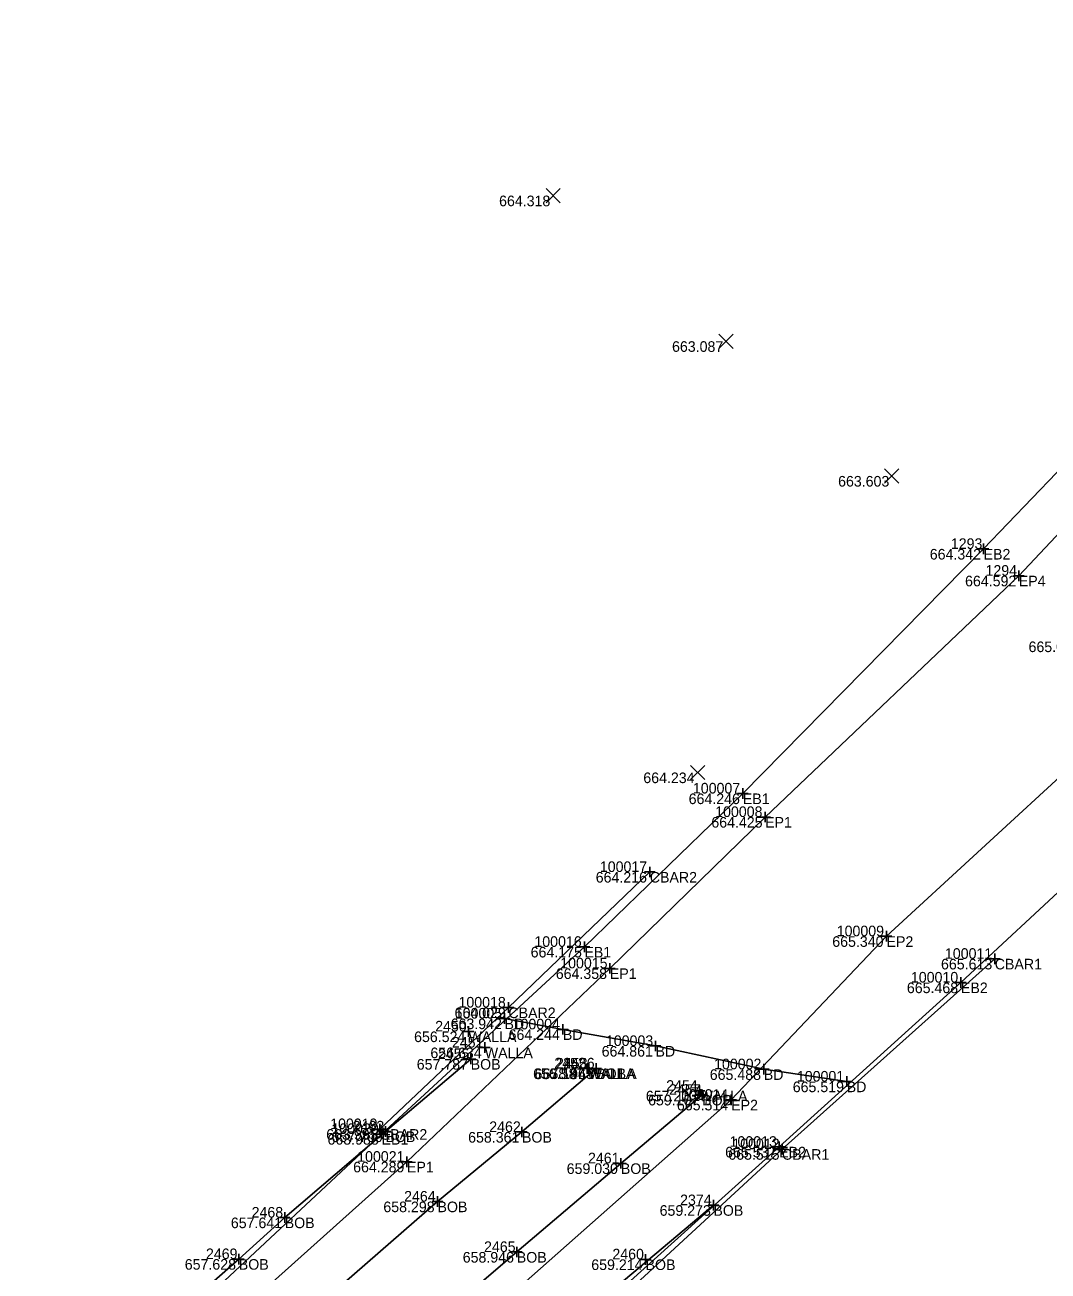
# Model space of a CAD drawing. Extents: x 2197382 to 2204062, y 634117 to 636522.
# Drawn here: x 2202757.5 to 2202854.1, y 635445.9 to 635563.6 of the extents above; entities that cross this region are included whole.
import ezdxf

# ---------------------------------------------------------------- set-up
doc = ezdxf.new("R2010")
doc.units = 0
for name, color, linetype in [('_CIVIL_CONSTRUCTION', 7, 'Continuous'), ('BR_X_SV_Abut', 7, 'Continuous'), ('BR_X_SV_Abut_Text', 7, 'Continuous'), ('BR_X_SV_Bottom_of_Beam', 7, 'Continuous'), ('BR_X_SV_Bottom_of_Beam_Text', 7, 'Continuous'), ('BR_X_SV_Deck_Top', 7, 'Continuous'), ('BR_X_SV_Deck_Top_Text', 7, 'Continuous'), ('GE_P_Alignment_100_Distances', 7, 'Continuous'), ('GE_X_Alignment', 7, 'Continuous'), ('RD_X_Concrete_Barrier', 7, 'Continuous'), ('RW_X_CL_100_Curve_Data', 7, 'Continuous'), ('SH_Border', 7, 'Continuous'), ('SH_Cut_Line', 7, 'Continuous'), ('SH_Data', 7, 'Continuous')]:
    doc.layers.add(name, color=color, linetype=linetype)

msp = doc.modelspace()

# ---------------------------------------------------------------- linework, layer by layer
at = {"layer": '_CIVIL_CONSTRUCTION'}
for p, q in [((2202847.99, 635514.61), (2202847.99, 635513.61)), ((2202847.49, 635514.11), (2202848.49, 635514.11)), ((2202847.99, 635514.11), (2202847.99, 635514.11)), ((2202850.81, 635511.58), (2202851.81, 635511.58)), ((2202851.31, 635512.08), (2202851.31, 635511.08)), ((2202851.31, 635511.58), (2202851.31, 635511.58)), ((2202824.77, 635491.02), (2202825.77, 635491.02)), ((2202825.27, 635491.52), (2202825.27, 635490.52)), ((2202825.27, 635491.02), (2202825.27, 635491.02)), ((2202826.87, 635488.8), (2202827.87, 635488.8)), ((2202827.37, 635489.3), (2202827.37, 635488.3)), ((2202827.37, 635488.8), (2202827.37, 635488.8)), ((2202816.49, 635484.11), (2202816.49, 635483.11)), ((2202815.99, 635483.61), (2202816.99, 635483.61)), ((2202816.49, 635483.61), (2202816.49, 635483.61)), ((2202838.83, 635478.04), (2202838.83, 635477.04)), ((2202810.32, 635477.04), (2202810.32, 635476.04)), ((2202838.33, 635477.54), (2202839.33, 635477.54)), ((2202838.83, 635477.54), (2202838.83, 635477.54)), ((2202809.82, 635476.54), (2202810.82, 635476.54)), ((2202810.32, 635476.54), (2202810.32, 635476.54)), ((2202849.04, 635475.91), (2202849.04, 635474.91)), ((2202812.22, 635474.51), (2202813.22, 635474.51)), ((2202812.72, 635475.01), (2202812.72, 635474.01)), ((2202812.72, 635474.51), (2202812.72, 635474.51)), ((2202848.54, 635475.41), (2202849.54, 635475.41)), ((2202849.04, 635475.41), (2202849.04, 635475.41)), ((2202845.85, 635473.67), (2202845.85, 635472.67)), ((2202845.35, 635473.17), (2202846.35, 635473.17)), ((2202845.85, 635473.17), (2202845.85, 635473.17)), ((2202803.15, 635471.31), (2202803.15, 635470.31)), ((2202802.28, 635469.77), (2202803.28, 635469.77)), ((2202802.65, 635470.81), (2202803.65, 635470.81)), ((2202802.78, 635470.27), (2202802.78, 635469.27)), ((2202802.78, 635469.77), (2202802.78, 635469.77)), ((2202803.15, 635470.81), (2202803.15, 635470.81)), ((2202799.38, 635469.05), (2202799.38, 635468.05)), ((2202807.79, 635468.75), (2202808.79, 635468.75)), ((2202808.29, 635469.25), (2202808.29, 635468.25)), ((2202808.29, 635468.75), (2202808.29, 635468.75)), ((2202798.88, 635468.55), (2202799.88, 635468.55)), ((2202799.38, 635468.55), (2202799.38, 635468.55)), ((2202800.92, 635467.53), (2202800.92, 635466.53)), ((2202817.03, 635467.68), (2202817.03, 635466.68)), ((2202799.59, 635466.45), (2202799.59, 635465.45)), ((2202800.42, 635467.03), (2202801.42, 635467.03)), ((2202800.92, 635467.03), (2202800.92, 635467.03)), ((2202816.53, 635467.18), (2202817.53, 635467.18)), ((2202817.03, 635467.18), (2202817.03, 635467.18)), ((2202799.09, 635465.95), (2202800.09, 635465.95)), ((2202799.59, 635465.95), (2202799.59, 635465.95)), ((2202810.57, 635465.56), (2202810.57, 635464.56)), ((2202810.73, 635465.55), (2202810.73, 635464.55)), ((2202811.43, 635465.56), (2202811.43, 635464.56)), ((2202827.25, 635465.48), (2202827.25, 635464.48)), ((2202810.07, 635465.06), (2202811.07, 635465.06)), ((2202810.23, 635465.05), (2202811.23, 635465.05)), ((2202810.57, 635465.06), (2202810.57, 635465.06)), ((2202810.73, 635465.05), (2202810.73, 635465.05)), ((2202810.93, 635465.06), (2202811.93, 635465.06)), ((2202811.43, 635465.06), (2202811.43, 635465.06)), ((2202826.75, 635464.98), (2202827.75, 635464.98)), ((2202827.25, 635464.98), (2202827.25, 635464.98)), ((2202835.07, 635464.32), (2202835.07, 635463.32)), ((2202820.68, 635462.95), (2202821.68, 635462.95)), ((2202821.18, 635463.45), (2202821.18, 635462.45)), ((2202821.18, 635462.95), (2202821.18, 635462.95)), ((2202821.43, 635463.07), (2202821.43, 635462.07)), ((2202834.57, 635463.82), (2202835.57, 635463.82)), ((2202835.07, 635463.82), (2202835.07, 635463.82)), ((2202820.93, 635462.57), (2202821.93, 635462.57)), ((2202821.43, 635462.57), (2202821.43, 635462.57)), ((2202823.67, 635462.1), (2202824.67, 635462.1)), ((2202824.17, 635462.6), (2202824.17, 635461.6)), ((2202824.17, 635462.1), (2202824.17, 635462.1)), ((2202790.53, 635459.33), (2202791.53, 635459.33)), ((2202791.03, 635459.83), (2202791.03, 635458.83)), ((2202791.03, 635459.33), (2202791.03, 635459.33)), ((2202791.18, 635459.37), (2202791.18, 635458.37)), ((2202791.54, 635459.61), (2202791.54, 635458.61)), ((2202804.43, 635459.56), (2202804.43, 635458.56)), ((2202790.68, 635458.87), (2202791.68, 635458.87)), ((2202791.04, 635459.11), (2202792.04, 635459.11)), ((2202791.18, 635458.87), (2202791.18, 635458.87)), ((2202791.54, 635459.11), (2202791.54, 635459.11)), ((2202803.93, 635459.06), (2202804.93, 635459.06)), ((2202804.43, 635459.06), (2202804.43, 635459.06)), ((2202828.7, 635458.16), (2202828.7, 635457.16)), ((2202828.2, 635457.66), (2202829.2, 635457.66)), ((2202828.47, 635457.44), (2202829.47, 635457.44)), ((2202828.7, 635457.66), (2202828.7, 635457.66)), ((2202828.97, 635457.94), (2202828.97, 635456.94)), ((2202828.97, 635457.44), (2202828.97, 635457.44)), ((2202793.08, 635456.25), (2202794.08, 635456.25)), ((2202793.58, 635456.75), (2202793.58, 635455.75)), ((2202793.58, 635456.25), (2202793.58, 635456.25)), ((2202813.26, 635456.1), (2202814.26, 635456.1)), ((2202813.76, 635456.6), (2202813.76, 635455.6)), ((2202813.76, 635456.1), (2202813.76, 635456.1)), ((2202795.96, 635452.49), (2202796.96, 635452.49)), ((2202796.46, 635452.99), (2202796.46, 635451.99)), ((2202796.46, 635452.49), (2202796.46, 635452.49)), ((2202821.99, 635452.15), (2202822.99, 635452.15)), ((2202822.49, 635452.65), (2202822.49, 635451.65)), ((2202822.49, 635452.15), (2202822.49, 635452.15)), ((2202781.54, 635450.98), (2202782.54, 635450.98)), ((2202782.04, 635451.48), (2202782.04, 635450.48)), ((2202782.04, 635450.98), (2202782.04, 635450.98)), ((2202777.71, 635447.56), (2202777.71, 635446.56)), ((2202803.44, 635447.73), (2202804.44, 635447.73)), ((2202803.94, 635448.23), (2202803.94, 635447.23)), ((2202803.94, 635447.73), (2202803.94, 635447.73)), ((2202816.09, 635447.53), (2202816.09, 635446.53)), ((2202777.21, 635447.06), (2202778.21, 635447.06)), ((2202777.71, 635447.06), (2202777.71, 635447.06)), ((2202815.59, 635447.03), (2202816.59, 635447.03)), ((2202816.09, 635447.03), (2202816.09, 635447.03))]:
    msp.add_line(p, q, dxfattribs=at)
at = {"layer": 'BR_X_SV_Abut'}
for p, q in [((2202799.38, 635468.55), (2202799.38, 635468.55)), ((2202800.92, 635467.03), (2202800.92, 635467.03)), ((2202810.57, 635465.06), (2202810.57, 635465.06)), ((2202810.73, 635465.05), (2202810.73, 635465.05)), ((2202821.18, 635462.95), (2202821.18, 635462.95))]:
    msp.add_line(p, q, dxfattribs=at)
at = {"layer": 'BR_X_SV_Bottom_of_Beam'}
for points in [[(2202799.59, 635465.95), (2202791.54, 635459.11), (2202782.04, 635450.98), (2202777.71, 635447.06), (2202760.7, 635432.08)], [(2202768.03, 635427.42), (2202775.97, 635434.66), (2202784.22, 635441.83), (2202796.46, 635452.49), (2202804.43, 635459.06), (2202811.43, 635465.06)], [(2202821.43, 635462.57), (2202813.76, 635456.1), (2202803.94, 635447.73), (2202790.38, 635436.09), (2202788.52, 635433.73)], [(2202550.74, 635261.3), (2202572.99, 635273.89), (2202594.56, 635285.88), (2202604.1, 635291.31), (2202615.23, 635297.56), (2202632.64, 635308.41), (2202649.92, 635319.32), (2202686.54, 635342.9), (2202715.55, 635365.05), (2202734.55, 635379.54), (2202765.2, 635403.19), (2202782.89, 635418.27), (2202797.35, 635430.62), (2202810.64, 635442.16), (2202822.49, 635452.15)]]:
    msp.add_lwpolyline(points, dxfattribs=at)
at = {"layer": 'BR_X_SV_Deck_Top'}
msp.add_line((2202769.74, 635438.84), (2202791.18, 635458.87), dxfattribs=at)
msp.add_lwpolyline([(2202835.07, 635463.82), (2202827.25, 635464.98), (2202817.03, 635467.18), (2202808.29, 635468.75), (2202802.78, 635469.77)], dxfattribs=at)
at = {"layer": 'GE_P_Alignment_100_Distances'}
for p, q in [((2202827.37, 635488.8), (2202851.31, 635511.58)), ((2202863.17, 635499.96), (2202838.83, 635477.54)), ((2202767.82, 635433.18), (2202793.58, 635456.25))]:
    msp.add_line(p, q, dxfattribs=at)
for points in [[(2203324.48, 636507.85), (2203318.62, 636484.14), (2203306.91, 636435.63), (2203294.22, 636387.53), (2203281.02, 636340.01), (2203266.86, 636291.74), (2203251.88, 636244.73), (2203235.99, 636197.91), (2203219.31, 636150.6), (2203201.96, 636104.73), (2203183.73, 636058.36), (2203164.29, 636012.58), (2203144.31, 635966.64), (2203123.63, 635921.48), (2203102.28, 635876.46), (2203085.37, 635841.98), (2203051.94, 635779.64), (2203032.08, 635745.73), (2203005.62, 635703.58), (2202977.57, 635663.01), (2202948.44, 635623.54), (2202917.31, 635585.47), (2202885.13, 635547.53), (2202851.31, 635511.58)], [(2202827.37, 635488.8), (2202812.72, 635474.51), (2202793.58, 635456.25)], [(2202838.83, 635477.54), (2202824.17, 635462.1), (2202802.91, 635443.29)]]:
    msp.add_lwpolyline(points, dxfattribs=at)
at = {"layer": 'GE_X_Alignment'}
for p, q in [((2202825.27, 635491.02), (2202847.99, 635514.11)), ((2202845.85, 635473.17), (2202868.61, 635494.33))]:
    msp.add_line(p, q, dxfattribs=at)
for points in [[(2203321.2, 636508.87), (2203315.42, 636484.99), (2203303.56, 636436.4), (2203290.91, 636388.48), (2203277.67, 636341.19), (2203263.29, 636292.83), (2203248.5, 636245.95), (2203232.65, 636199.01), (2203215.82, 636151.66), (2203198.58, 636105.93), (2203180.2, 636059.59), (2203161.3, 636014.11), (2203141.29, 635968.09), (2203120.26, 635923.09), (2203098.92, 635878.1), (2203081.73, 635843.65), (2203048.56, 635781.48), (2203029.15, 635747.49), (2203002.61, 635705.63), (2202974.64, 635665.31), (2202945.56, 635625.56), (2202914.38, 635588.2), (2202882.41, 635550.01), (2202847.99, 635514.11)], [(2202825.27, 635491.02), (2202810.32, 635476.54), (2202791.18, 635458.87)], [(2202845.85, 635473.17), (2202828.7, 635457.66), (2202807.02, 635438.1)]]:
    msp.add_lwpolyline(points, dxfattribs=at)
at = {"layer": 'RD_X_Concrete_Barrier'}
for points in [[(2202816.49, 635483.61), (2202803.15, 635470.81), (2202791.03, 635459.33)], [(2202849.04, 635475.41), (2202828.97, 635457.44), (2202807.47, 635437.58)]]:
    msp.add_lwpolyline(points, dxfattribs=at)
at = {"layer": 'RW_X_CL_100_Curve_Data'}
for p, q in [((2202806.71, 635546.8), (2202808.04, 635548.14)), ((2202806.71, 635548.14), (2202808.04, 635546.8)), ((2202823.01, 635533.05), (2202824.35, 635534.39)), ((2202823.01, 635534.39), (2202824.35, 635533.05)), ((2202838.65, 635520.33), (2202839.99, 635521.67)), ((2202838.65, 635521.67), (2202839.99, 635520.33)), ((2202820.34, 635492.34), (2202821.67, 635493.67)), ((2202820.34, 635493.67), (2202821.67, 635492.34))]:
    msp.add_line(p, q, dxfattribs=at)

# ---------------------------------------------------------------- texts
at = {"layer": 'BR_X_SV_Abut_Text'}
for s, p in [('2450', (2202796.24, 635468.55)), ('656.524', (2202794.25, 635467.55)), ('2451', (2202797.82, 635467.03)), ('WALLA', (2202799.38, 635467.55)), ('656.634', (2202795.79, 635466.03)), ('WALLA', (2202800.92, 635466.03)), ('656.587', (2202805.48, 635464.06)), ('657.196', (2202805.62, 635464.05)), ('2452', (2202807.48, 635465.06)), ('2453', (2202807.64, 635465.05)), ('WALLA', (2202810.57, 635464.06)), ('WALLA', (2202810.73, 635464.05)), ('2454', (2202818.04, 635462.95)), ('657.203', (2202816.12, 635461.95)), ('WALLA', (2202821.18, 635461.95))]:
    msp.add_text(s, height=1, dxfattribs=at).set_placement(p)
at = {"layer": 'BR_X_SV_Bottom_of_Beam_Text'}
for s, p in [('2455', (2202796.5, 635465.95)), ('657.787', (2202794.5, 635464.95)), ('BOB', (2202799.59, 635464.95)), ('658.443', (2202806.37, 635464.06)), ('2456', (2202808.31, 635465.06)), ('BOB', (2202811.43, 635464.06)), ('2457', (2202818.31, 635462.57)), ('659.107', (2202816.33, 635461.57)), ('BOB', (2202821.43, 635461.57)), ('2463', (2202788.46, 635459.11)), ('2462', (2202801.34, 635459.06)), ('657.709', (2202786.46, 635458.11)), ('BOB', (2202791.54, 635458.11)), ('658.361', (2202799.35, 635458.06)), ('BOB', (2202804.43, 635458.06)), ('2461', (2202810.66, 635456.1)), ('659.030', (2202808.65, 635455.1)), ('BOB', (2202813.76, 635455.1)), ('2464', (2202793.31, 635452.49)), ('658.298', (2202791.35, 635451.49)), ('BOB', (2202796.46, 635451.49)), ('659.273', (2202817.42, 635451.15)), ('2374', (2202819.35, 635452.15)), ('BOB', (2202822.49, 635451.15)), ('657.641', (2202776.96, 635449.98)), ('2468', (2202778.92, 635450.98)), ('BOB', (2202782.04, 635449.98)), ('2465', (2202800.85, 635447.73)), ('2469', (2202774.61, 635447.06)), ('658.946', (2202798.84, 635446.73)), ('BOB', (2202803.94, 635446.73)), ('2460', (2202812.96, 635447.03)), ('657.628', (2202772.61, 635446.06)), ('BOB', (2202777.71, 635446.06)), ('659.214', (2202810.97, 635446.03)), ('BOB', (2202816.09, 635446.03))]:
    msp.add_text(s, height=1, dxfattribs=at).set_placement(p)
at = {"layer": 'BR_X_SV_Deck_Top_Text'}
for s, p in [('663.942', (2202797.7, 635468.77)), ('100005', (2202798.09, 635469.77)), ('BD', (2202802.78, 635468.77)), ('664.244', (2202803.17, 635467.75)), ('100004', (2202803.55, 635468.75)), ('BD', (2202808.29, 635467.75)), ('100003', (2202812.35, 635467.18)), ('664.861', (2202811.95, 635466.18)), ('BD', (2202817.03, 635466.18)), ('100002', (2202822.56, 635464.98)), ('665.488', (2202822.15, 635463.98)), ('BD', (2202827.25, 635463.98)), ('100001', (2202830.37, 635463.82)), ('665.519', (2202829.98, 635462.82)), ('BD', (2202835.07, 635462.82))]:
    msp.add_text(s, height=1, dxfattribs=at).set_placement(p)
at = {"layer": 'SH_Border'}
for s, p in [('EB2', (2202847.99, 635513.11)), ('EP4', (2202851.31, 635510.58)), ('EB1', (2202825.27, 635490.02)), ('EP1', (2202827.37, 635487.8)), ('CBAR2', (2202816.49, 635482.61)), ('EP2', (2202838.83, 635476.54)), ('EB1', (2202810.32, 635475.54)), ('EP1', (2202812.72, 635473.51)), ('CBAR1', (2202849.04, 635474.41)), ('EB2', (2202845.85, 635472.17)), ('CBAR2', (2202803.15, 635469.81)), ('EP2', (2202824.17, 635461.1)), ('CBAR2', (2202791.03, 635458.33)), ('EB1', (2202791.18, 635457.87)), ('EB2', (2202828.7, 635456.66)), ('CBAR1', (2202828.97, 635456.44)), ('EP1', (2202793.58, 635455.25))]:
    msp.add_text(s, height=1, dxfattribs=at).set_placement(p)
at = {"layer": 'SH_Cut_Line'}
for s, p in [('1293', (2202844.9, 635514.11)), ('1294', (2202848.17, 635511.58)), ('100007', (2202820.56, 635491.02)), ('100008', (2202822.66, 635488.8)), ('100017', (2202811.78, 635483.61)), ('100009', (2202834.13, 635477.54)), ('100016', (2202805.6, 635476.54)), ('100011', (2202844.34, 635475.41)), ('100015', (2202808.04, 635474.51)), ('100010', (2202841.13, 635473.17)), ('100018', (2202798.44, 635470.81)), ('100014', (2202819.43, 635462.1)), ('100019', (2202786.33, 635459.33)), ('100020', (2202786.45, 635458.87)), ('100013', (2202824.02, 635457.66)), ('100012', (2202824.28, 635457.44)), ('100021', (2202788.88, 635456.25))]:
    msp.add_text(s, height=1, dxfattribs=at).set_placement(p)
at = {"layer": 'SH_Data'}
for s, p in [('664.318', (2202802.27, 635546.47)), ('663.087', (2202818.59, 635532.72)), ('663.603', (2202834.26, 635520)), ('664.342', (2202842.91, 635513.11)), ('664.592', (2202846.24, 635510.58)), ('665.046', (2202852.23, 635504.37)), ('664.234', (2202815.88, 635492)), ('664.246', (2202820.16, 635490.02)), ('664.425', (2202822.3, 635487.8)), ('664.216', (2202811.39, 635482.61)), ('665.340', (2202833.71, 635476.54)), ('664.175', (2202805.25, 635475.54)), ('664.358', (2202807.62, 635473.51)), ('665.613', (2202843.97, 635474.41)), ('665.468', (2202840.75, 635472.17)), ('664.029', (2202798.07, 635469.81)), ('665.514', (2202819.05, 635461.1)), ('663.995', (2202785.96, 635458.33)), ('663.988', (2202786.08, 635457.87)), ('665.537', (2202823.6, 635456.66)), ('665.515', (2202823.9, 635456.44)), ('664.289', (2202788.5, 635455.25))]:
    msp.add_text(s, height=1, dxfattribs=at).set_placement(p)

doc.saveas('drawing.dxf')
